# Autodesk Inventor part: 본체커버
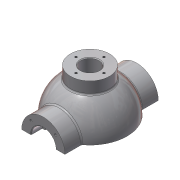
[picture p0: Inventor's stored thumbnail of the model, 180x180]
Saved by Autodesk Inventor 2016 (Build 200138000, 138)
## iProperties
Created: 2015-12
Part Number: 본체커버
Material: 알루미늄 6061
Document SubType Name: Modeling
Designer: mduedu
Density: 2.71 g/cm^3
Mass: 547.271 g
Surface Area: 428.16 cm^2
Volume: 201.945 cm^3
Appearance: 알루미늄 - 평지
Author: mduedu
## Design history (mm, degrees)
sketch "스케치1"
  geometry: L1 (-53, 0)-(53, 0); A1 r 53 centre (0, 0) between (53, 0) and (-53, 0); 2 further points
  constraints: 2 coincident, 2 end point, 2 point on circle, 1 centre point, 1 horizontal, 1 midpoint
  dimensions: "d0" = 53 radius of A1
revolve "회전1" sketch "스케치1" stored, may be unused: angle "d2" = 90 deg
feature "쉘1" dims "d11" = 10
node "작업 평면1"
sketch "스케치2"
  geometry: C1 r 31 at (0, 0); 1 further point
  constraints: 1 centre point, 1 coincident
  dimensions: "d4" = 62 diameter of C1
extrude "돌출1" join sketch "스케치2" stored distance "d5" = 10; taper "d6" = 0 deg
hole "구멍1" diameter "d14" = 35; stored, may be unused: countersink angle "d18" = 90 deg, drill point angle "d20" = 0 deg; dims "d12" = 10, "d13" = 10, "d15" = 6, "d16" = 4, "d17" = 2, "d19" = 16
hole "구멍2" diameter "d23" = 27; stored, may be unused: countersink angle "d27" = 90 deg, drill point angle "d29" = 0 deg; dims "d21" = 10, "d22" = 10, "d24" = 6, "d25" = 4, "d26" = 2, "d28" = 16
fillet "모깎기1" dims "d30" = 0.3
chamfer "모따기1" distance "d40" = 1; stored, may be unused: second distance "d41" = 2, angle "d42" = 45 deg
sketch "스케치4"
  geometry: L1 (0, 0)-(0, -25); L2 (0, 0)-(-17.678, -17.678); A1 r 25 centre (0, 0) between (-17.678, -17.678) and (0, -25); 1 further point
  constraints: 4 end point, 2 point on circle, 1 centre point, 1 coincident, 1 vertical
  dimensions: "d43" = 50 diameter of A1; "d47" = 45 deg angle of L1 L2
hole "구멍4" sketch "스케치4" at (-17.678, -17.678) diameter "d49" = 3.242; stored, may be unused: countersink angle "d53" = 90 deg, drill point angle "d55" = 118 deg; dims "d50" = 11, "d51" = 4, "d52" = 2, "d54" = 13
node "작업 평면3"
sketch "스케치6"
  geometry: C1 r 65 at (0, 0); 1 further point
  constraints: 1 centre point, 1 coincident
  dimensions: "d78" = 130 diameter of C1
extrude "돌출3" join sketch "스케치6" distance "d80" = 10; taper "d81" = 0 deg
sketch "스케치7"
  geometry: C1 r 20 at (0, 0); 1 further point
  constraints: 1 centre point, 1 coincident
  dimensions: "d82" = 40 diameter of C1
extrude "돌출4" join sketch "스케치7" stored distance "d84" = 10; taper "d85" = 0 deg
sketch "스케치8"
  geometry: 2 further points
  constraints: 1 coincident
hole "구멍6" sketch "스케치8" at (0, 0) diameter "d86" = 20; stored, may be unused: countersink angle "d90" = 90 deg, drill point angle "d92" = 118 deg; dims "d87" = 7, "d88" = 40, "d89" = 5, "d91" = 10
fillet "모깎기2" dims "d93" = 0.3
sketch "스케치9"
  geometry: L1 (65, -75)-(-65, -75) reference; L2 (-45, -75)-(-38.245, -36.692); A1 r 53 centre (0, 0) between (42.988, 31) and (42.988, -31) reference; 1 further point
  constraints: 2 end point, 1 point on circle, 1 point on line
  dimensions: "d94" = 45 horizontal distance of L2.start point (0, 0); "d95" = 80 deg angle of L2 L1
feature "리브1" sketch "스케치9" dims "d96" = 1, "d97" = 8, "d98" = 0, "d99" = 0, "d100" = 1, "d101" = 1
sketch "스케치10"
  geometry: L1 (0, 0)-(0, -55); L2 (0, 0)-(-38.891, -38.891); A1 r 55 centre (0, 0) between (0, -55) and (-38.891, -38.891); 2 further points
  constraints: 4 end point, 2 coincident, 2 point on circle, 1 centre point, 1 vertical
  dimensions: "d105" = 110 diameter of A1; "d107" = 45 deg angle of L1 L2
hole "구멍7" sketch "스케치10" at (-38.891, -38.891) diameter "d109" = 10; stored, may be unused: countersink angle "d113" = 90 deg, drill point angle "d115" = 118 deg; dims "d110" = 7, "d111" = 40, "d112" = 5, "d114" = 10
fillet "모깎기3" dims "d120" = 3
fillet "모깎기4" dims "d121" = 3, "d122" = 3
fillet "모깎기5" dims "d123" = 3
fillet "모깎기6" dims "d124" = 3
sketch "스케치11"
  geometry: C1 r 5 at (-38.891, 38.891) reference; C2 r 5 at (38.891, 38.891) reference; C3 r 5 at (38.891, -38.891) reference; C4 r 5 at (-38.891, -38.891) reference; C5 r 20 at (0, 0) reference; C6 r 65 at (0, 0) reference; 1 further point
  constraints: 3 other
feature "엠보싱1" sketch "스케치11" dims "d125" = 0.5, "d126" = 0
sketch "스케치12"
  geometry: L1 (0, 100)-(0, -100); L2 (0, 100)-(-150, 100); L3 (-150, 100)-(-150, -100); L4 (-150, -100)-(0, -100); 2 further points
  constraints: 8 end point, 3 perpendicular, 1 coincident, 1 midpoint, 1 vertical
  dimensions: "d127" = 200 distance of L2.end L3.end; "d129" = 150 distance of L3.end L1.end
extrude "돌출5" cut sketch "스케치12" stored distance "d130" = 10; taper "d131" = 0 deg
node "작업 평면4"
sketch "스케치16"
  geometry: C1 r 28 at (0, 0); 1 further point
  constraints: 1 centre point, 1 coincident
  dimensions: "d148" = 56 diameter of C1
extrude "돌출9" join sketch "스케치16" stored distance "d150" = 5; taper "d151" = 0 deg
hole "구멍8" diameter "d154" = 26; stored, may be unused: countersink angle "d158" = 90 deg, drill point angle "d160" = 118 deg; dims "d152" = 10, "d153" = 10, "d155" = 6, "d156" = 4, "d157" = 2, "d159" = 8
sketch "스케치17" dims "d161" = 40
  geometry: 3 further points
  constraints: 2 vertical alignment, 1 coincident, 2 other
hole "구멍9" sketch "스케치17" at (0, 20) diameter "d163" = 3.242; stored, may be unused: countersink angle "d167" = 90 deg, drill point angle "d169" = 118 deg; dims "d164" = 8, "d165" = 4, "d166" = 2, "d168" = 10
fillet "모깎기11" dims "d173" = 3
chamfer "모따기2" distance "d174" = 1; stored, may be unused: second distance "d175" = 2, angle "d176" = 45 deg
node "솔리드1"
mirror "대칭1"
mirror "대칭2"
pattern_circular "원형 패턴1" dims angle "d57" = 360 deg
mirror "대칭3"
pattern_circular "원형 패턴3" dims angle "d103" = 360 deg
pattern_circular "원형 패턴4" dims "d40" = 1, angle "d118" = 360 deg
pattern_circular "원형 패턴5" dims angle "d171" = 360 deg
node "투영된 루프1"
other parameters: "d3" = 67, "d77" = -85, "d147" = 62
